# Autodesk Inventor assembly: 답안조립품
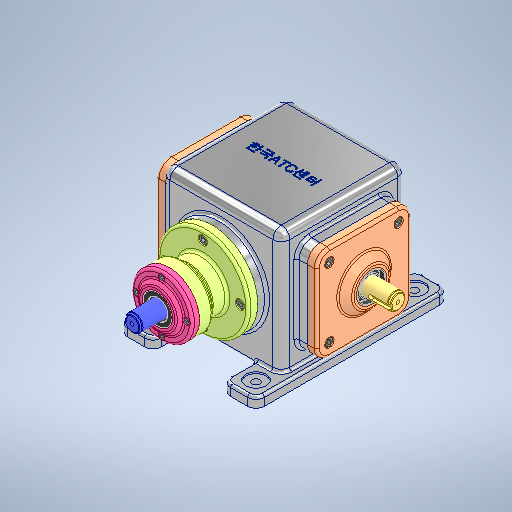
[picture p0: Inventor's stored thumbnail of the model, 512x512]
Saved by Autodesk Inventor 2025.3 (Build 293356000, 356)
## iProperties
Created: 2026-01
Part Number: 답안조립품
Document SubType Name: Assembly
Designer: PC-13
Author: PC-13
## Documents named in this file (16)
- C:\Users\PC-13\Desktop\760103V1012\답안조립품.iam
- C:\Users\PC-13\Desktop\760103V1012\본체.ipt
- C:\Users\PC-13\Desktop\760103V1012\760103V1012\베벨 기어(종동)\베벨 기어(종동).ipt
- C:\Users\PC-13\Desktop\760103V1012\760103V1012\종동축\종동축.ipt
- C:\Users\PC-13\Desktop\760103V1012\760103V1012\평행 키 6x6x18\평행 키 6x6x18.ipt
- C:\Users\PC-13\Desktop\760103V1012\760103V1012\측면 커버\측면 커버.ipt
- C:\Users\PC-13\Desktop\760103V1012\760103V1012\칼라\칼라.ipt
- C:\Users\PC-13\Desktop\760103V1012\760103V1012\테이퍼 롤러 베어링 30204K\테이퍼 롤러 베어링 30204K.ipt
- C:\Users\PC-13\Desktop\760103V1012\760103V1012\6각 구멍붙이 볼트 M6x12\6각 구멍붙이 볼트 M6x12.ipt
- C:\Users\PC-13\Desktop\760103V1012\760103V1012\베어링 하우징\베어링 하우징.ipt
- C:\Users\PC-13\Desktop\760103V1012\760103V1012\오일 실 20 35 8\오일 실 20 35 8.ipt
- C:\Users\PC-13\Desktop\760103V1012\760103V1012\6각 구멍붙이 볼트 M4x10\6각 구멍붙이 볼트 M4x10.ipt
- C:\Users\PC-13\Desktop\760103V1012\760103V1012\구동축\구동축.ipt
- C:\Users\PC-13\Desktop\760103V1012\760103V1012\베벨 기어(구동)\베벨 기어(구동).ipt
- C:\Users\PC-13\Desktop\760103V1012\760103V1012\엔드캡\엔드캡.ipt
- C:\Users\PC-13\Desktop\760103V1012\760103V1012\하우징 커버\하우징 커버.ipt
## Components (19 placed, 4 different names)
1. 6각 구멍붙이 볼트 M6x12:1
2. 6각 구멍붙이 볼트 M6x12:2
3. 6각 구멍붙이 볼트 M6x12:3
4. 6각 구멍붙이 볼트 M6x12:4
5. 구동축:1
6. 하우징 커버:1
7. 6각 구멍붙이 볼트 M6x12:5
8. 6각 구멍붙이 볼트 M6x12:6
9. 6각 구멍붙이 볼트 M6x12:7
10. 6각 구멍붙이 볼트 M6x12:8
11. 6각 구멍붙이 볼트 M6x12:9
12. 6각 구멍붙이 볼트 M6x12:10
13. 6각 구멍붙이 볼트 M6x12:11
14. 6각 구멍붙이 볼트 M6x12:12
15. 6각 구멍붙이 볼트 M6x12:13
16. 6각 구멍붙이 볼트 M4x10:1
17. 6각 구멍붙이 볼트 M4x10:2
18. 6각 구멍붙이 볼트 M4x10:3
19. 6각 구멍붙이 볼트 M4x10:4
